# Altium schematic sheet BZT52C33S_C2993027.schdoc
size 127 x 101 mm
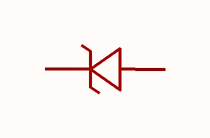
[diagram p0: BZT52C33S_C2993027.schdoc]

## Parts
D?  bzt52c33s_c2993027  [SOD-323_L1.6-W1.3-LS2.7-RD]  (value not drawn)

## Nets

Not connected (* = marked no-connect by the designer): D? 1(K) 2(A)

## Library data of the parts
D? = bzt52c33s_c2993027: 二极管配置:1个独立式;稳压值(标称值):33V;稳压值(范围):31V~35V;耗散功率(Pd):200mW;; Manufacturer: MDD(辰达半导体); AddInBom: yes; ModelId: 39bca86493a8419684ee2090e9340edf; ModelTransform: 104.3305,51.181,0,0,0,0,0,0,0; Diode Configuration: 1个独立式; Zener Voltage(Nom): 33V; Reverse Leakage Current (Ir): 100nA@25V; Pd - Power Dissipation: 200mW; Impedance(Zzt): 80Ω; Tolerance: ±5%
